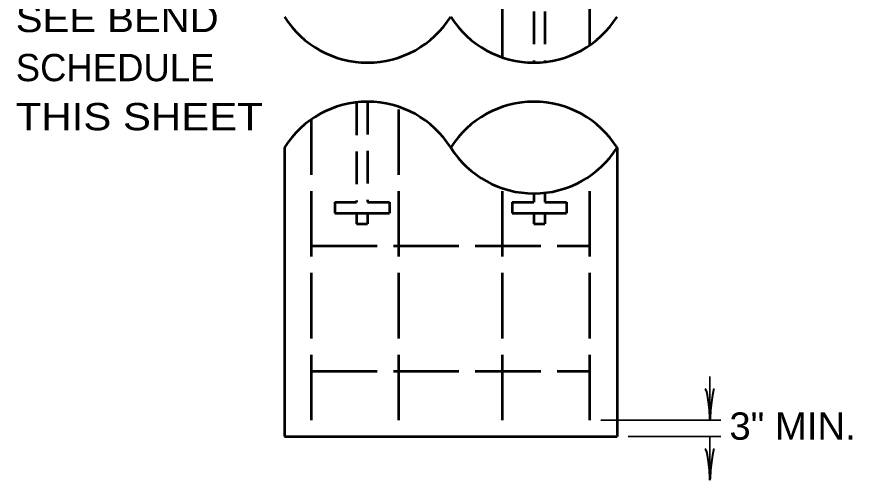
# Model space of a CAD drawing. Extents: x -68 to 612, y -58 to 382.
# Drawn here: x 154.3 to 230.9, y 92.5 to 135 of the extents above; entities that cross this region are included whole.
import ezdxf

# ---------------------------------------------------------------- set-up
doc = ezdxf.new("R2010")
doc.units = 0
doc.linetypes.add('LONG_DASHED', pattern=[7.5, 6, -1.5])
doc.linetypes.add('MEDIUM_DASHED', pattern=[4.5, 3, -1.5])
doc.layers.add('1', color=7, linetype='Continuous', lineweight=53)

msp = doc.modelspace()

# ---------------------------------------------------------------- linework, layer by layer
at = {"layer": '1', "linetype": 'MEDIUM_DASHED'}
for p, q in [((201.741, 180.515), (201.741, 130.818)), ((202.741, 180.515), (202.741, 130.873)), ((185.491, 127.177), (185.491, 118.025)), ((186.491, 127.233), (186.491, 118.025)), ((201.741, 118.818), (201.741, 118.025)), ((202.741, 118.873), (202.741, 118.025)), ((185.491, 117.025), (185.491, 116.025)), ((186.491, 117.025), (186.491, 116.025)), ((201.741, 117.025), (201.741, 116.025)), ((202.741, 117.025), (202.741, 116.025))]:
    msp.add_line(p, q, dxfattribs=at)
at = {"layer": '1', "linetype": 'LONG_DASHED'}
for p, q in [((198.866, 131.289), (198.866, 178.015)), ((206.866, 132.417), (206.866, 178.015)), ((189.366, 98.025), (189.366, 126.762)), ((181.366, 98.025), (181.366, 125.634)), ((206.866, 98.025), (206.866, 120.417)), ((198.866, 98.025), (198.866, 119.289)), ((183.491, 118.025), (183.491, 117.025)), ((183.491, 118.025), (185.491, 118.025)), ((186.491, 118.025), (188.491, 118.025)), ((188.491, 118.025), (188.491, 117.025)), ((199.741, 118.025), (199.741, 117.025)), ((199.741, 118.025), (201.741, 118.025)), ((202.741, 118.025), (204.741, 118.025)), ((204.741, 118.025), (204.741, 117.025)), ((183.491, 117.025), (188.491, 117.025)), ((199.741, 117.025), (204.741, 117.025)), ((185.491, 116.025), (186.491, 116.025)), ((201.741, 116.025), (202.741, 116.025)), ((181.366, 114.025), (206.866, 114.025)), ((181.366, 102.525), (206.866, 102.525))]:
    msp.add_line(p, q, dxfattribs=at)
at = {"layer": '1'}
for p, q in [((178.866, 123.025), (178.866, 96.525)), ((209.366, 123.025), (209.366, 96.525)), ((178.866, 96.525), (209.366, 96.525))]:
    msp.add_line(p, q, dxfattribs=at)
at = {"layer": '1', "lineweight": 35}
for p, q in [((217.866, 98.025), (217.866, 102.025)), ((207.866, 98.025), (218.866, 98.025)), ((210.366, 96.525), (218.866, 96.525)), ((217.866, 96.525), (217.866, 92.525))]:
    msp.add_line(p, q, dxfattribs=at)
at = {"layer": '1'}
for centre, start, end in [((186.491, 139.83), 212.21779, 327.78222), ((201.741, 139.83), 212.21779, 327.78222), ((186.491, 118.22), 32.21779, 147.78222), ((201.741, 118.22), 32.21779, 147.78222), ((201.741, 127.83), 212.21778, 327.78221)]:
    msp.add_arc(centre, 9.013, start, end, dxfattribs=at)
at = {"layer": '1', "lineweight": 40}
for centre, major_axis, ratio, start_param, end_param in [((217.59, 99.117), (0.156, -1.786), 0.122415, 0.896353, 3.141593), ((218.078, 99.146), (-0.176, -1.756), 0.07063, 3.140715, 5.41811), ((217.59, 93.617), (0.156, -1.786), 0.122415, 0.896353, 3.141593), ((218.078, 93.646), (-0.176, -1.756), 0.07063, 3.140715, 5.41811)]:
    msp.add_ellipse(centre, major_axis=major_axis, ratio=ratio, start_param=start_param, end_param=end_param, dxfattribs=at)

# ---------------------------------------------------------------- texts
at = {"layer": '1'}
for s, width, p in [('SEE BEND', 1.1, (154.249, 133.612)), ('THIS SHEET', 1.15, (154.249, 124.612)), ('3" MIN.', 1.05, (219.658, 96.238))]:
    msp.add_text(s, height=2.5, dxfattribs=dict(at, width=width)).set_placement(p)
msp.add_text('SCHEDULE', height=2.5, dxfattribs=at).set_placement((154.249, 129.112))

doc.saveas('drawing.dxf')
